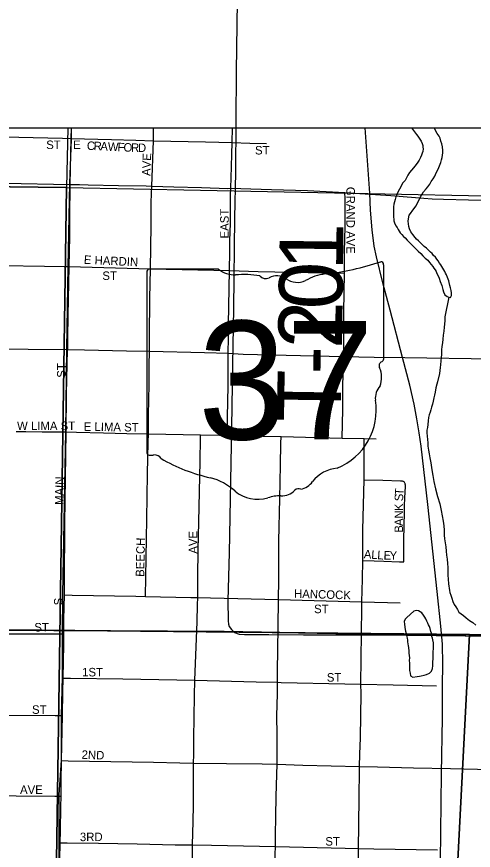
# Model space of a CAD drawing. Extents: x 0 to 68, y 0 to 52.9.
# Drawn here: x 43.878 to 44.415, y 37.686 to 38.666 of the extents above; entities that cross this region are included whole.
import ezdxf

# ---------------------------------------------------------------- set-up
doc = ezdxf.new("R2010")
doc.units = 0
for name, color, linetype in [('Default', 7, 'Continuous'), ('GM_X_Minor_Lake', 7, 'Continuous'), ('GM_X_Minor_River', 7, 'Continuous'), ('GM_X_State_Route', 7, 'Continuous'), ('GM_X_State_Shield', 7, 'Continuous'), ('GM_X_Township', 7, 'Continuous'), ('GM_X_Township_Road', 7, 'Continuous'), ('GM_X_Township_Road_Text', 7, 'Continuous')]:
    doc.layers.add(name, color=color, linetype=linetype)

msp = doc.modelspace()

# ---------------------------------------------------------------- linework, layer by layer
at = {"layer": 'Default'}
msp.add_line((42.25806, 38.53508), (49.65006, 38.53508), dxfattribs=at)
for points in [[(43.1609, 39.26536), (44.47349, 39.25009), (44.45233, 37.93902), (44.41032, 37.93957), (43.13273, 37.95279)], [(42.87499, 38.47751), (43.93627, 38.46518), (43.9204, 37.41034), (42.85875, 37.42389)], [(43.93627, 38.46518), (44.96064, 38.44451), (44.96032, 37.38586), (43.92065, 37.39833), (43.9204, 37.41034)], [(43.13273, 37.95279), (44.41032, 37.93957), (44.34414, 36.66665), (43.11555, 36.67874)], [(44.41032, 37.93957), (44.45233, 37.93902), (45.7586, 37.9073), (45.68961, 36.62483), (44.34414, 36.66665)]]:
    msp.add_lwpolyline(points, close=True, dxfattribs=at)
for points in [[(43.93775, 38.53508), (43.93627, 38.46518), (42.87499, 38.47751), (42.87603, 38.53508)], [(44.03851, 38.52008), (44.03851, 38.53508)], [(44.1309, 38.51777), (44.13132, 38.53508)], [(44.37484, 37.56941), (44.37737, 37.77621), (44.37821, 37.84156), (44.37855, 37.87945), (44.37872, 37.90488), (44.37821, 37.92846), (44.37653, 37.94951), (44.37206, 37.99035), (44.36103, 38.09232), (44.35328, 38.16088), (44.35104, 38.17662), (44.34838, 38.19318), (44.34511, 38.21045), (44.34, 38.23274), (44.33151, 38.26544), (44.3169, 38.32105), (44.30841, 38.35314), (44.30065, 38.3837), (44.29819, 38.39617), (44.29574, 38.41518), (44.2938, 38.43839), (44.29278, 38.45842), (44.28751, 38.53508)], [(44.34206, 38.53508), (44.34788, 38.5275), (44.34944, 38.52546), (44.35178, 38.52181), (44.35333, 38.51937), (44.35449, 38.51694), (44.35524, 38.51451), (44.3552, 38.51251), (44.35556, 38.5105), (44.3551, 38.5073), (44.35465, 38.5053), (44.3538, 38.50291), (44.35254, 38.50013), (44.35088, 38.49735), (44.3484, 38.49379), (44.34592, 38.49023), (44.34427, 38.48826), (44.34181, 38.4855)], [(44.35902, 38.46348), (44.36108, 38.46585), (44.36355, 38.46901), (44.36522, 38.47219), (44.36729, 38.47535), (44.36936, 38.47852), (44.37104, 38.4821), (44.37272, 38.48568), (44.37398, 38.48846), (44.37566, 38.49244), (44.37651, 38.49443), (44.37737, 38.49762), (44.37783, 38.50042), (44.37829, 38.50322), (44.37874, 38.50562), (44.3788, 38.50842), (44.37849, 38.51284), (44.37776, 38.51647), (44.37662, 38.5197), (44.37548, 38.52293), (44.37432, 38.52536), (44.37198, 38.52862), (44.36846, 38.53508)], [(43.84537, 38.52491), (43.9313, 38.52298), (43.94146, 38.52275)], [(43.94146, 38.52275), (43.98923, 38.52155), (44.01779, 38.52056), (44.03851, 38.52008)], [(44.03657, 38.46668), (44.03851, 38.52008)], [(44.03851, 38.52008), (44.09952, 38.51864), (44.1309, 38.51777)], [(44.12946, 38.46411), (44.13014, 38.48942), (44.13054, 38.50441), (44.1309, 38.51777)], [(44.1309, 38.51777), (44.15182, 38.51719), (44.17151, 38.51664)], [(44.34181, 38.4855), (44.33975, 38.48273), (44.33768, 38.47956), (44.33601, 38.47639), (44.33434, 38.47321), (44.33146, 38.47006), (44.32937, 38.46569), (44.32771, 38.46291), (44.32604, 38.45974), (44.32478, 38.45695), (44.32352, 38.45417), (44.32265, 38.45098), (44.32179, 38.44819), (44.32133, 38.44539), (44.32086, 38.44219), (44.3208, 38.43898), (44.32062, 38.43015), (44.32097, 38.42774), (44.32133, 38.42573), (44.3221, 38.42371), (44.32363, 38.42006), (44.32519, 38.41803), (44.32634, 38.4156), (44.32868, 38.41194), (44.33064, 38.40989), (44.3326, 38.40745), (44.33457, 38.4058), (44.33693, 38.40335), (44.33929, 38.40089), (44.34165, 38.39844), (44.3444, 38.39557), (44.34716, 38.39311), (44.34991, 38.39025), (44.35306, 38.38737), (44.35542, 38.38492), (44.35817, 38.38205), (44.36133, 38.37959), (44.36328, 38.37674), (44.36525, 38.37469), (44.3672, 38.37224), (44.36837, 38.37021), (44.36993, 38.36818), (44.37109, 38.36615), (44.37185, 38.36413), (44.3734, 38.36129), (44.37455, 38.35846), (44.37567, 38.35442), (44.37759, 38.34997), (44.37869, 38.34513), (44.37944, 38.34231), (44.38098, 38.33907), (44.38375, 38.33701), (44.38573, 38.33616), (44.38773, 38.33572), (44.38899, 38.3381), (44.38905, 38.34131), (44.38871, 38.34413), (44.38796, 38.34695), (44.38721, 38.34977), (44.38608, 38.35341), (44.38573, 38.35542), (44.38496, 38.35744), (44.3842, 38.35947), (44.38306, 38.3623), (44.38189, 38.36433), (44.38113, 38.36635), (44.37997, 38.36838), (44.3788, 38.37041), (44.37647, 38.37406), (44.37491, 38.3761), (44.37336, 38.37894), (44.3718, 38.38098), (44.37023, 38.38302), (44.36786, 38.38507), (44.36631, 38.38751), (44.36434, 38.38915), (44.36197, 38.39121), (44.35961, 38.39366), (44.35684, 38.39572), (44.35449, 38.39818), (44.35212, 38.40023), (44.35015, 38.40228), (44.34779, 38.40433), (44.34622, 38.40637), (44.34348, 38.40963), (44.34114, 38.41289), (44.33961, 38.41653), (44.33886, 38.41936), (44.33852, 38.42217), (44.33818, 38.42539), (44.33824, 38.4282), (44.33913, 38.43259), (44.34078, 38.43456), (44.34367, 38.43852), (44.34738, 38.44366), (44.34989, 38.44842), (44.35156, 38.452), (44.35283, 38.45478), (44.35448, 38.45716), (44.35614, 38.45993), (44.35902, 38.46348)], [(43.84411, 38.47042), (43.86371, 38.47017), (43.9401, 38.46868)], [(44.03479, 38.36942), (44.03558, 38.42029), (44.03592, 38.44782), (44.03657, 38.46668)], [(44.12792, 38.36738), (44.12828, 38.39001), (44.12831, 38.40294), (44.12896, 38.42268), (44.12888, 38.43587), (44.12925, 38.45622), (44.12946, 38.46411)], [(44.26295, 38.36435), (44.26326, 38.3898), (44.26375, 38.41902), (44.26378, 38.43758), (44.26372, 38.45218), (44.26368, 38.45917)], [(43.84249, 38.37365), (43.86053, 38.37349), (43.9103, 38.37267), (43.93324, 38.37222), (43.9388, 38.37218)], [(43.9388, 38.37218), (44.03479, 38.36942)], [(44.0338, 38.27257), (44.03384, 38.28531), (44.03391, 38.3036), (44.03413, 38.32037), (44.0343, 38.33449), (44.03479, 38.36942)], [(44.03479, 38.36942), (44.12792, 38.36738)], [(44.12639, 38.27017), (44.12674, 38.2882), (44.12651, 38.29802), (44.12681, 38.3046), (44.12792, 38.36738)], [(44.12792, 38.36738), (44.16147, 38.36646), (44.18135, 38.36598), (44.19784, 38.36558), (44.22044, 38.36503), (44.26295, 38.36435)], [(44.26199, 38.26653), (44.26221, 38.2808), (44.26241, 38.31848), (44.26295, 38.36435)], [(43.84082, 38.27585), (43.89117, 38.27503), (43.93727, 38.27455)], [(43.9357, 38.17778), (43.93636, 38.22197), (43.93727, 38.27455)], [(44.03252, 38.17547), (44.03267, 38.20094), (44.03284, 38.2118), (44.03323, 38.23721), (44.03351, 38.25571), (44.0338, 38.27257)], [(44.12509, 38.17356), (44.12596, 38.21468), (44.12617, 38.23077), (44.12624, 38.26247), (44.12639, 38.27017)], [(44.26032, 38.17064), (44.26109, 38.20423), (44.2613, 38.22926), (44.26199, 38.26653)], [(43.87705, 38.17823), (43.8883, 38.17824), (43.90759, 38.17805), (43.92392, 38.17776), (43.9357, 38.17778)], [(43.9338, 37.98619), (43.93379, 37.99977), (43.93418, 38.07067), (43.93462, 38.09689), (43.93533, 38.15028), (43.9357, 38.17778)], [(43.9357, 38.17778), (43.94796, 38.17731), (43.97973, 38.1769), (44.00715, 38.17606), (44.03252, 38.17547)], [(44.02891, 37.9843), (44.03061, 38.07512), (44.03145, 38.12837), (44.03229, 38.16587), (44.03252, 38.17547)], [(44.03252, 38.17547), (44.09392, 38.17423)], [(44.09049, 37.98306), (44.09081, 38.00785), (44.09115, 38.03888), (44.09165, 38.07199), (44.09326, 38.14289), (44.09381, 38.17034), (44.09392, 38.17423)], [(44.09392, 38.17423), (44.11623, 38.17381), (44.12509, 38.17356)], [(44.12509, 38.17356), (44.18862, 38.17231)], [(44.18563, 37.98068), (44.18605, 38.00379), (44.18609, 38.04944), (44.18722, 38.0997), (44.18786, 38.13887), (44.18842, 38.16419), (44.18862, 38.17231)], [(44.18862, 38.17231), (44.26032, 38.17064)], [(44.26032, 38.17064), (44.28638, 38.17005)], [(44.28617, 38.12142), (44.28638, 38.16551), (44.28638, 38.17005)], [(44.28638, 38.17005), (44.30026, 38.1698)], [(44.28471, 38.02665), (44.28484, 38.06283), (44.28617, 38.12142)], [(44.28617, 38.12142), (44.30802, 38.1209), (44.32898, 38.12043), (44.32985, 38.12038), (44.33091, 38.12026), (44.33166, 38.12009), (44.33221, 38.11984), (44.33301, 38.11933)], [(44.33283, 38.02499), (44.33307, 38.03417), (44.33297, 38.05053), (44.33357, 38.08381), (44.33369, 38.09092), (44.33405, 38.1004), (44.33468, 38.11379), (44.33475, 38.11533), (44.33461, 38.11652), (44.33447, 38.11713), (44.33424, 38.11772), (44.33382, 38.11845), (44.33336, 38.119), (44.33301, 38.11933)], [(44.28352, 37.97818), (44.28422, 38.00466), (44.28471, 38.02665)], [(44.28471, 38.02665), (44.29817, 38.02619), (44.30926, 38.02575), (44.32783, 38.02497), (44.33283, 38.02499)], [(43.93312, 37.94035), (43.93323, 37.95719), (43.9338, 37.98619)], [(43.9338, 37.98619), (43.94285, 37.98606), (44.01778, 37.98494), (44.02891, 37.9843)], [(44.02891, 37.9843), (44.08256, 37.98312), (44.09049, 37.98306)], [(44.08701, 37.88591), (44.08978, 37.95465), (44.09037, 37.97438), (44.09049, 37.98306)], [(44.09049, 37.98306), (44.10536, 37.98261), (44.18563, 37.98068)], [(44.18433, 37.8836), (44.18448, 37.8964), (44.18531, 37.94835), (44.18563, 37.98068)], [(44.18563, 37.98068), (44.28352, 37.97818)], [(44.28237, 37.88148), (44.28351, 37.97049), (44.28352, 37.97818)], [(44.28352, 37.97818), (44.32853, 37.97705)], [(43.83619, 37.94051), (43.84381, 37.94044), (43.92183, 37.94037), (43.93312, 37.94035)], [(43.93231, 37.88855), (43.93267, 37.90803), (43.93304, 37.92765), (43.93312, 37.94035)], [(43.93148, 37.84452), (43.93201, 37.87198), (43.93231, 37.88855)], [(43.93231, 37.88855), (43.94076, 37.88843), (44.00258, 37.88755), (44.08701, 37.88591)], [(44.08572, 37.78847), (44.0861, 37.79869), (44.08609, 37.81791), (44.0864, 37.84219), (44.08687, 37.86808), (44.08701, 37.88591)], [(44.08701, 37.88591), (44.15931, 37.88419), (44.18433, 37.8836)], [(44.18375, 37.78717), (44.1838, 37.82187), (44.18355, 37.84393), (44.18417, 37.87013), (44.18433, 37.8836)], [(44.18433, 37.8836), (44.18881, 37.88345), (44.26369, 37.88162), (44.28237, 37.88148)], [(44.28088, 37.78471), (44.28134, 37.7989), (44.28195, 37.81811), (44.28254, 37.8703), (44.28237, 37.88148)], [(44.28237, 37.88148), (44.32052, 37.88057), (44.37116, 37.8792)], [(43.74177, 37.84555), (43.78628, 37.84534), (43.83811, 37.84494), (43.92279, 37.84456), (43.93148, 37.84452)], [(43.93046, 37.79149), (43.93148, 37.84452)], [(43.92977, 37.74977), (43.92999, 37.76656), (43.93046, 37.79149)], [(43.93046, 37.79149), (43.9382, 37.79135), (44.03856, 37.78953), (44.06954, 37.78873), (44.08572, 37.78847)], [(44.08452, 37.69253), (44.08506, 37.7198), (44.0854, 37.73931), (44.08572, 37.78847)], [(44.08572, 37.78847), (44.12426, 37.78801), (44.16642, 37.78766), (44.18375, 37.78717)], [(44.18183, 37.69044), (44.18197, 37.70341), (44.18223, 37.72616), (44.18294, 37.74933), (44.18349, 37.77528), (44.18375, 37.78717)], [(44.18375, 37.78717), (44.21419, 37.78632), (44.28088, 37.78471)], [(44.27966, 37.68814), (44.2798, 37.71606), (44.28046, 37.74847), (44.28069, 37.78001), (44.28088, 37.78471)], [(44.28088, 37.78471), (44.30189, 37.78421), (44.34421, 37.7832), (44.38776, 37.78219), (44.43533, 37.78123)], [(43.74046, 37.75084), (43.7601, 37.75072), (43.81678, 37.75047), (43.87684, 37.75027), (43.92254, 37.74984), (43.92977, 37.74977)], [(43.9288, 37.69499), (43.92914, 37.70893), (43.92962, 37.73724), (43.92977, 37.74977)], [(43.92792, 37.65649), (43.9288, 37.69499)], [(43.9288, 37.69499), (43.93714, 37.69467), (43.97375, 37.69446), (44.01937, 37.69356), (44.06395, 37.69268), (44.08452, 37.69253)], [(44.08323, 37.61505), (44.08404, 37.64599), (44.08422, 37.66182), (44.08452, 37.69253)], [(44.08452, 37.69253), (44.10687, 37.69201), (44.18183, 37.69044)], [(44.181, 37.61351), (44.18172, 37.68113), (44.18183, 37.69044)], [(44.18183, 37.69044), (44.26375, 37.68858), (44.27966, 37.68814)], [(44.27835, 37.59175), (44.27939, 37.64045), (44.27966, 37.68814)], [(44.27966, 37.68814), (44.29781, 37.68782), (44.3725, 37.68645)]]:
    msp.add_lwpolyline(points, dxfattribs=at)
at = {"layer": 'GM_X_Minor_Lake'}
for points in [[(44.34454, 37.96707), (44.33636, 37.95962), (44.33431, 37.95765), (44.33345, 37.95486), (44.3338, 37.95204), (44.33413, 37.94843), (44.33447, 37.94561), (44.33483, 37.9436), (44.33558, 37.94077), (44.33593, 37.93836), (44.33667, 37.93554), (44.33703, 37.93312), (44.33739, 37.93111), (44.33774, 37.92869), (44.33809, 37.92628), (44.33845, 37.92427), (44.33877, 37.92025), (44.33872, 37.91784), (44.33907, 37.91503), (44.33941, 37.91221), (44.33935, 37.909), (44.33969, 37.90619), (44.33964, 37.90378), (44.33959, 37.90137), (44.33955, 37.89937), (44.33951, 37.89736), (44.34025, 37.89414), (44.34059, 37.89132), (44.34337, 37.88966), (44.3486, 37.89036), (44.35142, 37.8907), (44.35343, 37.89107), (44.35666, 37.8918), (44.35948, 37.89255), (44.36312, 37.89408), (44.36558, 37.89644), (44.36645, 37.89963), (44.36691, 37.90283), (44.36695, 37.90483), (44.36701, 37.90764), (44.36749, 37.91124), (44.36756, 37.91485), (44.36725, 37.91927), (44.36773, 37.92328), (44.3678, 37.92689), (44.36787, 37.93009), (44.36713, 37.93332), (44.36677, 37.93533), (44.36601, 37.93735), (44.36565, 37.93937), (44.36529, 37.94138), (44.36453, 37.9434), (44.36379, 37.94662), (44.36303, 37.94905), (44.36187, 37.95108), (44.36111, 37.9531), (44.35996, 37.95553), (44.3588, 37.95796), (44.35764, 37.95999), (44.35608, 37.96243), (44.35413, 37.96528), (44.35016, 37.96736)], [(44.35016, 37.96736), (44.34736, 37.96782), (44.34454, 37.96707)]]:
    msp.add_lwpolyline(points, dxfattribs=at)
at = {"layer": 'GM_X_Minor_River'}
msp.add_lwpolyline([(44.38573, 38.33616), (44.38125, 38.31298), (44.38116, 38.30857), (44.38068, 38.30457), (44.38021, 38.30097), (44.38011, 38.29616), (44.37921, 38.29136), (44.37872, 38.28696), (44.37823, 38.28255), (44.37774, 38.27815), (44.37725, 38.27415), (44.37715, 38.26893), (44.37667, 38.26533), (44.37659, 38.26132), (44.37609, 38.25652), (44.37563, 38.25332), (44.37516, 38.25012), (44.37469, 38.24651), (44.37248, 38.23653), (44.37162, 38.23374), (44.37073, 38.22974), (44.36982, 38.22455), (44.36895, 38.22095), (44.36808, 38.21776), (44.3676, 38.21376), (44.36673, 38.21056), (44.36546, 38.20698), (44.36459, 38.20379), (44.36373, 38.201), (44.36286, 38.1978), (44.36199, 38.19461), (44.36152, 38.19101), (44.36103, 38.18661), (44.36056, 38.18301), (44.36009, 38.1798), (44.36002, 38.1766), (44.36035, 38.17298), (44.36067, 38.16896), (44.36099, 38.16494), (44.36131, 38.16092), (44.36202, 38.1565), (44.36274, 38.15207), (44.36344, 38.14724), (44.36453, 38.1416), (44.36596, 38.13315), (44.36704, 38.12671), (44.3681, 38.11946), (44.37033, 38.11099), (44.37255, 38.10172), (44.37519, 38.09324), (44.37664, 38.08559), (44.37811, 38.07914), (44.37919, 38.0731), (44.37988, 38.06747), (44.38018, 38.06225), (44.38047, 38.05662), (44.38078, 38.0522), (44.38148, 38.04738), (44.38219, 38.04255), (44.38289, 38.03772), (44.3832, 38.0329), (44.3839, 38.02807), (44.38421, 38.02325), (44.38451, 38.01843), (44.38482, 38.01401), (44.38473, 38.0096), (44.38503, 38.00477), (44.38532, 37.99915), (44.38677, 37.9915), (44.38712, 37.98909), (44.38826, 37.98585), (44.38939, 37.98222), (44.39052, 37.97858), (44.39205, 37.97494), (44.394, 37.97209), (44.39595, 37.96925), (44.39749, 37.96601), (44.40026, 37.96395), (44.40303, 37.96188), (44.40619, 37.95941), (44.41013, 37.95612), (44.4141, 37.95364), (44.41765, 37.95076)], dxfattribs=at)
at = {"layer": 'GM_X_State_Route'}
for points in [[(43.9416, 38.53508), (43.94146, 38.52275), (43.9401, 38.46868)], [(43.9401, 38.46868), (43.93956, 38.43047), (43.93965, 38.40737), (43.9388, 38.37218), (43.9376, 38.31464), (43.93724, 38.28812), (43.93727, 38.27455)], [(43.9401, 38.46868), (43.95164, 38.46858), (43.96151, 38.46832), (43.99733, 38.46751), (44.02993, 38.46686), (44.03657, 38.46668), (44.06248, 38.46601), (44.09506, 38.46512), (44.12593, 38.46407), (44.12946, 38.46411)], [(44.12946, 38.46411), (44.15301, 38.46346), (44.17714, 38.46274), (44.21961, 38.46145), (44.26368, 38.45917), (44.27511, 38.45858), (44.31751, 38.4558), (44.34682, 38.45337), (44.3664, 38.45171), (44.37952, 38.45117), (44.43845, 38.44987), (44.44553, 38.44971), (44.47631, 38.44893)], [(43.93727, 38.27455), (43.95751, 38.27431), (44.00666, 38.27323), (44.0338, 38.27257), (44.09838, 38.27099), (44.12639, 38.27017), (44.1441, 38.26931), (44.26199, 38.26653), (44.29804, 38.26568), (44.33408, 38.26543), (44.43779, 38.26365)]]:
    msp.add_lwpolyline(points, dxfattribs=at)
at = {"layer": 'GM_X_State_Shield'}
for p, q in [((44.11506, 38.3691), (44.03352, 38.3691)), ((44.30921, 38.26379), (44.30921, 38.37434)), ((44.03078, 38.36546), (44.03078, 38.15414)), ((44.30918, 38.26381), (44.30921, 38.26379))]:
    msp.add_line(p, q, dxfattribs=at)
for centre, radius, start, end in [((44.21003, 38.65721), 0.29527, 275.84447, 288.90645), ((44.30612, 38.37479), 0.0031, 351.86209, 97.738), ((44.03397, 38.36591), 0.00323, 98.1301, 188.1301), ((44.13448, 38.39363), 0.03129, 231.61951, 271.11188), ((44.14485, 38.25046), 0.11232, 80.48669, 94.98827), ((44.17035, 38.36701), 0.00903, 219.79206, 297.10237), ((44.1836, 38.34258), 0.01877, 54.46668, 119.14113), ((44.24769, 38.30455), 0.0594, 97.34618, 120.76885), ((44.20782, 38.37608), 0.02258, 233.85621, 294.82819), ((44.3085, 38.25567), 0.0048, 107.94398, 210.33697), ((44.30591, 38.26336), 0.00332, 289.60381, 7.73413), ((44.27798, 38.2417), 0.0288, 340.03296, 23.64957), ((44.32032, 38.21752), 0.02095, 136.8065, 186.92959), ((44.22657, 38.20346), 0.07385, 292.30889, 8.98584), ((44.034, 38.15367), 0.00325, 171.95839, 258.30661), ((44.03449, 38.17529), 0.02483, 267.33899, 280.60386), ((44.03957, 38.14194), 0.00895, 29.74838, 93.27175), ((44.15263, 38.33181), 0.21323, 240.41292, 257.1985), ((44.25771, 38.09481), 0.04045, 94.40312, 142.57675), ((44.08906, 38.0592), 0.06672, 47.18416, 75.83597), ((44.20646, 38.13365), 0.02386, 282.87319, 323.27711), ((44.16121, 38.14089), 0.04233, 230.70037, 286.29184), ((44.18877, 38.12507), 0.02256, 268.77702, 315.54927), ((44.20917, 38.1046), 0.00635, 65.75173, 132.64842), ((44.18567, 38.06783), 0.03479, 85.69512, 111.20995)]:
    msp.add_arc(centre, radius, start, end, dxfattribs=at)
at = {"layer": 'GM_X_Township'}
for points in [[(50.34506, 37.77433), (49.87003, 37.78728), (49.7424, 37.78907), (49.09193, 37.81286), (48.42924, 37.83782), (47.97584, 37.8521), (47.09341, 37.87493), (46.43542, 37.88698), (45.78152, 37.90751), (45.76356, 37.9078), (44.77759, 37.93161), (44.12143, 37.94309), (43.3203, 37.94792), (43.31455, 37.9477), (43.13228, 37.95106), (43.13722, 38.12535), (43.1394, 38.18651), (43.13947, 38.19396), (43.15039, 38.61621), (43.15805, 38.89613)], [(43.92717, 37.65807), (43.92754, 37.69421), (43.92773, 37.75121), (43.93024, 37.79183), (43.93024, 37.84399), (43.93155, 37.89), (43.93155, 37.94012), (43.93192, 37.98688), (43.93523, 38.17887), (43.93645, 38.2756), (43.93818, 38.37234), (43.94005, 38.47027), (43.94196, 38.52189), (43.94208, 38.53508)], [(43.06441, 32.7683), (43.08393, 33.99592), (43.08445, 34.02868), (43.09249, 34.65268), (43.09292, 34.68642), (43.10458, 35.31419), (43.1053, 35.34562), (43.1113, 36.01383), (43.1191, 36.64269), (43.12347, 37.01757), (43.12518, 37.25841), (43.12908, 37.42523), (43.12464, 37.49311), (43.12504, 37.51468), (43.13199, 37.8314), (43.13205, 37.85841), (43.13228, 37.95106), (43.31455, 37.9477), (43.3203, 37.94792), (44.12143, 37.94309), (44.77759, 37.93161), (45.76356, 37.9078)]]:
    msp.add_lwpolyline(points, dxfattribs=at)
at = {"layer": 'GM_X_Township_Road'}
for points in [[(44.1418, 39.25679), (44.14087, 39.18433), (44.14014, 39.09), (44.13786, 38.85211), (44.13762, 38.80768), (44.13799, 38.77667), (44.13763, 38.7612), (44.13683, 38.68355), (44.13568, 38.60174), (44.13482, 38.48286), (44.13376, 38.42954), (44.13259, 38.32291), (44.13138, 38.25729), (44.13025, 38.18347), (44.12737, 38.03584), (44.12595, 37.97973), (44.12641, 37.9556), (44.12664, 37.95176), (44.12731, 37.94896), (44.13006, 37.94547)], [(44.13006, 37.94547), (44.13366, 37.9422), (44.13919, 37.94017), (44.1456, 37.93958), (44.15418, 37.93958), (44.17426, 37.93982), (44.21509, 37.93939), (44.30327, 37.93917), (44.43863, 37.93782), (44.51244, 37.93583), (44.56165, 37.93528), (44.63137, 37.93387), (44.7872, 37.93047)]]:
    msp.add_lwpolyline(points, dxfattribs=at)

# ---------------------------------------------------------------- texts
at = {"layer": 'Default'}
for s, rotation, p in [('ST', 0.00001, (43.91233, 38.51025)), ('E', 0.00001, (43.94402, 38.51025)), ('C', 357.40075, (43.95994, 38.50937)), ('R', 357.42668, (43.96786, 38.50901)), ('A', 357.39843, (43.97577, 38.50866)), ('W', 357.41324, (43.98456, 38.50826)), ('F', 357.41632, (43.99599, 38.50774)), ('O', 357.39843, (44.00302, 38.50742)), ('R', 358.22421, (44.01197, 38.50702)), ('D', 359.77872, (44.02018, 38.50677)), ('ST', 0.00001, (44.15786, 38.50386)), ('AVE', 88.02609, (44.03489, 38.47848)), ('GRAND AVE', 270, (44.26534, 38.46586)), ('EAST', 90, (44.12693, 38.40514)), ('E HARDIN', 357.39879, (43.95642, 38.37534)), ('ST', 0.00001, (43.97834, 38.35637)), ('ST', 90, (43.93509, 38.24146)), ('W LIMA ST', 0.00001, (43.87802, 38.17998)), ('E LIMA ST', 359.14534, (43.95636, 38.1791)), ('MAIN', 88.78506, (43.93245, 38.0918)), ('S', 88.05989, (44.33199, 38.09617)), ('T', 85.65158, (44.33222, 38.10309)), ('K', 89.97034, (44.33199, 38.08482)), ('N', 89.97034, (44.33198, 38.07602)), ('A', 89.95627, (44.33198, 38.06722)), ('B', 89.9757, (44.33197, 38.0593)), ('AVE', 90, (44.08997, 38.03466)), ('BEECH', 88.75525, (44.0275, 38.00742)), ('A', 356.01872, (44.2856, 38.02937)), ('L', 356.02506, (44.29438, 38.02876)), ('L', 356.03508, (44.3014, 38.02827)), ('E', 359.05283, (44.309, 38.02776)), ('Y', 359.84624, (44.31619, 38.02764)), ('HANCOCK', 358.34063, (44.20367, 37.98286)), ('S', 90, (43.93157, 37.97394)), ('ST', 0.00001, (44.22738, 37.96478)), ('ST', 0.00001, (43.89826, 37.94326)), ('1ST', 0.00001, (43.95457, 37.89046)), ('ST', 0.00001, (44.24233, 37.8843)), ('ST', 0.00001, (43.89562, 37.84646)), ('2ND', 357.8801, (43.95377, 37.79366)), ('AVE', 0.00001, (43.88153, 37.7523)), ('3RD', 0.00001, (43.95194, 37.69686)), ('ST', 0.00001, (44.24057, 37.69158))]:
    msp.add_text(s, height=0.01, rotation=rotation, dxfattribs=at).set_placement(p)
at = {"layer": 'GM_X_State_Shield'}
msp.add_text('37', height=0.139219, dxfattribs=at).set_placement((44.09085, 38.16904))
at = {"layer": 'GM_X_Township_Road_Text'}
for s, rotation, p in [('1', 89.32342, (44.26133, 38.36735)), ('0', 89.30383, (44.26078, 38.32149)), ('2', 89.03096, (44.25999, 38.27528)), ('-', 89.00884, (44.25947, 38.24472)), ('T', 89.11307, (44.2586, 38.18877))]:
    msp.add_text(s, height=0.075, rotation=rotation, dxfattribs=at).set_placement(p)

doc.saveas('drawing.dxf')
